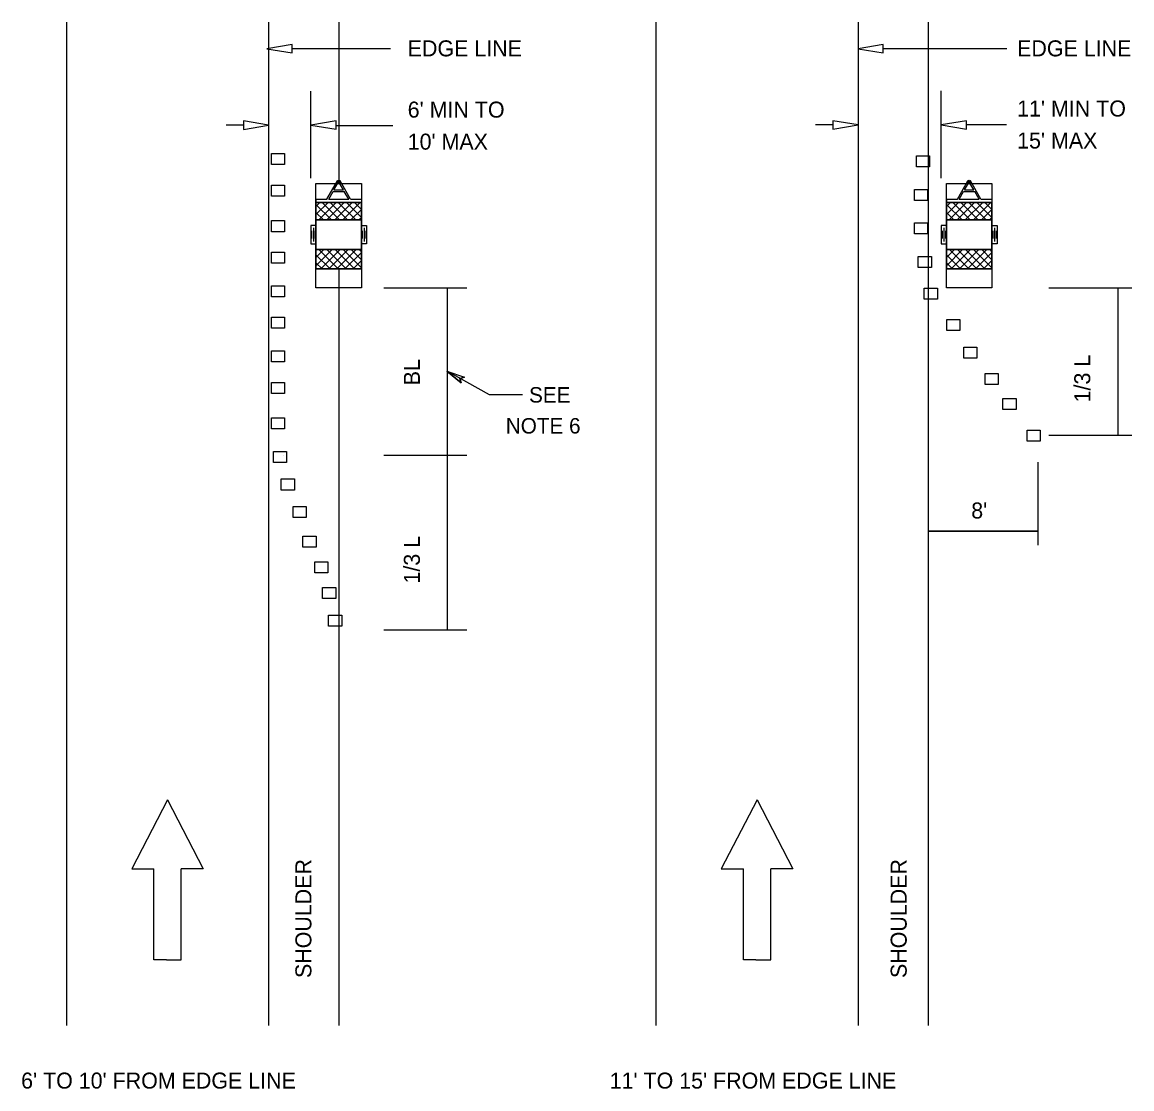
# Model space of a CAD drawing. Extents: x 9 to 25.8, y 6 to 22.7.
# Drawn here: x 21.457 to 25.758, y 11.055 to 15.19 of the extents above; entities that cross this region are included whole.
import ezdxf

# ---------------------------------------------------------------- set-up
doc = ezdxf.new("R2010")
doc.units = 0
for name, color, linetype in [('C-SIGN-FACE_N', 7, 'Continuous'), ('DETL-DIMS', 7, 'Continuous'), ('DETL-LINE', 7, 'Continuous'), ('DETL-NOTE', 7, 'Continuous'), ('SIGN-FACE_P', 7, 'Continuous'), ('SIGN-POST_VSL', 7, 'Continuous'), ('TRAF-MISC', 7, 'Continuous'), ('USER-BORD', 7, 'Continuous')]:
    doc.layers.add(name, color=color, linetype=linetype)

# ---------------------------------------------------------------- blocks, each defined once
blk = doc.blocks.new('DIR2')
at = {"layer": 'USER-BORD'}
for p, q in [((0, 0.0001), (-0.0034, -0.0048)), ((0, 0.0001), (0.0034, -0.0048)), ((-0.0034, -0.0048), (-0.0013, -0.0048)), ((-0.0013, -0.0113), (-0.0013, -0.0048)), ((0.0034, -0.0048), (0.0013, -0.0048)), ((0.0013, -0.0113), (0.0013, -0.0048)), ((-0.0001, -0.0113), (-0.0013, -0.0113)), ((-0.0001, -0.0113), (0.0001, -0.0113)), ((0.0001, -0.0113), (0.0013, -0.0113))]:
    blk.add_line(p, q, dxfattribs=at)

msp = doc.modelspace()

# ---------------------------------------------------------------- linework, layer by layer
at = {"layer": 'C-SIGN-FACE_N'}
for points in [[(22.5956, 14.4912), (22.7718, 14.4912), (22.7718, 14.2335), (22.5956, 14.2335)], [(25.0393, 14.4912), (25.2154, 14.4912), (25.2154, 14.2335), (25.0393, 14.2335)]]:
    msp.add_lwpolyline(points, close=True, dxfattribs=at)
at = {"layer": 'DETL-DIMS'}
for p, q in [((22.5025, 15.0887), (22.8844, 15.0887)), ((24.7931, 15.0887), (25.2736, 15.0887)), ((22.5755, 14.5852), (22.5755, 14.9233)), ((25.0192, 14.5859), (25.0192, 14.924)), ((22.3141, 14.7909), (22.2472, 14.7909)), ((22.6733, 14.789), (22.893, 14.789)), ((24.599, 14.7918), (24.5321, 14.7918)), ((25.116, 14.7934), (25.2724, 14.7934)), ((22.8587, 14.1603), (23.1805, 14.1603)), ((23.1047, 14.1603), (23.1047, 12.8339)), ((23.1047, 14.1603), (23.1047, 13.511)), ((25.4358, 14.1603), (25.7576, 14.1603)), ((25.7029, 14.1603), (25.7029, 13.5895)), ((25.7029, 14.1603), (25.7029, 13.5895)), ((23.1026, 13.8373), (23.1587, 13.7913)), ((23.1026, 13.8373), (23.1711, 13.8132)), ((23.2678, 13.7452), (23.104, 13.837)), ((23.1532, 13.8089), (23.1711, 13.8132)), ((23.1587, 13.7913), (23.1532, 13.8089)), ((23.396, 13.7452), (23.2678, 13.7452)), ((25.4358, 13.5895), (25.7576, 13.5895)), ((22.8587, 13.511), (23.1805, 13.511)), ((23.1047, 13.511), (23.1047, 12.8339)), ((25.3931, 13.4841), (25.3931, 13.1623)), ((24.9685, 13.217), (25.3931, 13.217)), ((25.3931, 13.217), (24.9685, 13.217)), ((22.8587, 12.8339), (23.1805, 12.8339))]:
    msp.add_line(p, q, dxfattribs=at)
for points in [[(22.5038, 15.0707), (22.5038, 15.1034), (22.4058, 15.087)], [(24.7944, 15.0707), (24.7944, 15.1034), (24.6964, 15.087)], [(22.3141, 14.8073), (22.3141, 14.7746), (22.4121, 14.7909)], [(22.6736, 14.7747), (22.6736, 14.8074), (22.5755, 14.791)], [(24.599, 14.8081), (24.599, 14.7754), (24.697, 14.7918)], [(25.1172, 14.7754), (25.1172, 14.8081), (25.0192, 14.7918)], [(23.1587, 13.7913), (23.1026, 13.8373), (23.1711, 13.8132), (23.1532, 13.8089)]]:
    msp.add_lwpolyline(points, close=True, dxfattribs=at)
at = {"layer": 'DETL-LINE'}
for p, q in [((21.6284, 15.1901), (21.6284, 11.3001)), ((22.4121, 15.1901), (22.4121, 11.3001)), ((22.6837, 15.1901), (22.6837, 14.5775)), ((23.9133, 15.1901), (23.9133, 11.3001)), ((24.697, 15.1901), (24.697, 11.3001)), ((24.9685, 15.1901), (24.9685, 11.3001)), ((22.6837, 14.2335), (22.6837, 11.3001)), ((22.4685, 13.511), (22.4685, 13.511))]:
    msp.add_line(p, q, dxfattribs=at)
for points in [[(22.4228, 14.6379), (22.4228, 14.6807), (22.4738, 14.6807), (22.4738, 14.6379)], [(24.9225, 14.629), (24.9225, 14.6718), (24.9735, 14.6718), (24.9735, 14.629)], [(22.4228, 14.5156), (22.4228, 14.5583), (22.4738, 14.5583), (22.4738, 14.5156)], [(24.9148, 14.499), (24.9148, 14.5418), (24.9657, 14.5418), (24.9657, 14.499)], [(22.4228, 14.3779), (22.4228, 14.4207), (22.4738, 14.4207), (22.4738, 14.3779)], [(24.9148, 14.369), (24.9148, 14.4118), (24.9657, 14.4118), (24.9657, 14.369)], [(22.4228, 14.2555), (22.4228, 14.2984), (22.4738, 14.2984), (22.4738, 14.2555)], [(24.9302, 14.239), (24.9302, 14.2818), (24.9811, 14.2818), (24.9811, 14.239)], [(22.4228, 14.1256), (22.4228, 14.1684), (22.4738, 14.1684), (22.4738, 14.1256)], [(24.953, 14.1167), (24.953, 14.1595), (25.004, 14.1595), (25.004, 14.1167)], [(22.4228, 14.0032), (22.4228, 14.0461), (22.4738, 14.0461), (22.4738, 14.0032)], [(25.0405, 13.9943), (25.0405, 14.0371), (25.0914, 14.0371), (25.0914, 13.9943)], [(22.4228, 13.8731), (22.4228, 13.916), (22.4738, 13.916), (22.4738, 13.8731)], [(25.1063, 13.8872), (25.1063, 13.9301), (25.1573, 13.9301), (25.1573, 13.8872)], [(25.1889, 13.7853), (25.1889, 13.8281), (25.2399, 13.8281), (25.2399, 13.7853)], [(22.4228, 13.7508), (22.4228, 13.7937), (22.4738, 13.7937), (22.4738, 13.7508)], [(25.2581, 13.6885), (25.2581, 13.7312), (25.309, 13.7312), (25.309, 13.6885)], [(22.4228, 13.6132), (22.4228, 13.6561), (22.4738, 13.6561), (22.4738, 13.6132)], [(25.3516, 13.566), (25.3516, 13.6089), (25.4025, 13.6089), (25.4025, 13.566)], [(22.4306, 13.4832), (22.4306, 13.526), (22.4815, 13.526), (22.4815, 13.4832)], [(22.4611, 13.3761), (22.4611, 13.419), (22.512, 13.419), (22.512, 13.3761)], [(22.5069, 13.2691), (22.5069, 13.3119), (22.5578, 13.3119), (22.5578, 13.2691)], [(22.5451, 13.1544), (22.5451, 13.1973), (22.596, 13.1973), (22.596, 13.1544)], [(22.5911, 13.0549), (22.5911, 13.0978), (22.6419, 13.0978), (22.6419, 13.0549)], [(22.6215, 12.9556), (22.6215, 12.9984), (22.6724, 12.9984), (22.6724, 12.9556)], [(22.6445, 12.8485), (22.6445, 12.8914), (22.6954, 12.8914), (22.6954, 12.8485)]]:
    msp.add_lwpolyline(points, close=True, dxfattribs=at)
at = {"layer": 'SIGN-FACE_P'}
for p, q in [((22.5956, 14.5044), (22.5956, 14.4912)), ((22.7718, 14.5044), (22.7718, 14.4912)), ((25.0393, 14.5044), (25.0393, 14.4912)), ((25.2154, 14.5044), (25.2154, 14.4912))]:
    msp.add_line(p, q, dxfattribs=at)
at = {"layer": 'SIGN-POST_VSL'}
for points in [[(22.5956, 14.5643), (22.7718, 14.5643), (22.7718, 14.1603), (22.5956, 14.1603)], [(25.0393, 14.5643), (25.2154, 14.5643), (25.2154, 14.1603), (25.0393, 14.1603)]]:
    msp.add_lwpolyline(points, close=True, dxfattribs=at)
at = {"layer": 'TRAF-MISC'}
for p, q in [((22.6381, 14.5044), (22.6786, 14.5746)), ((22.6653, 14.5397), (22.6808, 14.5665)), ((22.6653, 14.5397), (22.7021, 14.5397)), ((22.7021, 14.5397), (22.6867, 14.5665)), ((22.7294, 14.5044), (22.6888, 14.5746)), ((25.0817, 14.5044), (25.1222, 14.5746)), ((25.1089, 14.5397), (25.1244, 14.5665)), ((25.1089, 14.5397), (25.1458, 14.5397)), ((25.1458, 14.5397), (25.1303, 14.5665)), ((25.173, 14.5044), (25.1324, 14.5746)), ((22.5956, 14.5044), (22.6381, 14.5044)), ((22.6449, 14.5044), (22.6619, 14.5338)), ((22.6449, 14.5044), (22.7225, 14.5044)), ((22.6619, 14.5338), (22.7055, 14.5338)), ((22.7225, 14.5044), (22.7055, 14.5338)), ((22.7294, 14.5044), (22.7718, 14.5044)), ((25.0393, 14.5044), (25.0817, 14.5044)), ((25.0885, 14.5044), (25.1055, 14.5338)), ((25.0885, 14.5044), (25.1662, 14.5044)), ((25.1055, 14.5338), (25.1492, 14.5338)), ((25.1662, 14.5044), (25.1492, 14.5338)), ((25.173, 14.5044), (25.2154, 14.5044)), ((22.5956, 14.4912), (22.5956, 14.4236)), ((22.5956, 14.4444), (22.6424, 14.4912)), ((22.5956, 14.4757), (22.6111, 14.4912)), ((22.5956, 14.4839), (22.6559, 14.4236)), ((22.5956, 14.4526), (22.6247, 14.4236)), ((22.6061, 14.4236), (22.6736, 14.4912)), ((22.6196, 14.4912), (22.6872, 14.4236)), ((22.6373, 14.4236), (22.7049, 14.4912)), ((22.6509, 14.4912), (22.7184, 14.4236)), ((22.6686, 14.4236), (22.7361, 14.4912)), ((22.6821, 14.4912), (22.7497, 14.4236)), ((22.6998, 14.4236), (22.7674, 14.4912)), ((22.7134, 14.4912), (22.7718, 14.4328)), ((22.7311, 14.4236), (22.7718, 14.4643)), ((22.7446, 14.4912), (22.7718, 14.4641)), ((25.0393, 14.4912), (25.0393, 14.4236)), ((25.0393, 14.4444), (25.086, 14.4912)), ((25.0393, 14.4757), (25.0547, 14.4912)), ((25.0393, 14.4839), (25.0996, 14.4236)), ((25.0393, 14.4526), (25.0683, 14.4236)), ((25.0497, 14.4236), (25.1173, 14.4912)), ((25.0633, 14.4912), (25.1308, 14.4236)), ((25.081, 14.4236), (25.1485, 14.4912)), ((25.0945, 14.4912), (25.1621, 14.4236)), ((25.1122, 14.4236), (25.1798, 14.4912)), ((25.1258, 14.4912), (25.1933, 14.4236)), ((25.1435, 14.4236), (25.211, 14.4912)), ((25.157, 14.4912), (25.2154, 14.4328)), ((25.1747, 14.4236), (25.2154, 14.4643)), ((25.1883, 14.4912), (25.2154, 14.4641)), ((22.5956, 14.4236), (22.7718, 14.4236)), ((22.7623, 14.4236), (22.7718, 14.433)), ((25.0393, 14.4236), (25.2154, 14.4236)), ((25.206, 14.4236), (25.2154, 14.433)), ((22.5787, 14.381), (22.5787, 14.351)), ((22.5856, 14.3926), (22.5856, 14.3393)), ((22.5925, 14.381), (22.5925, 14.351)), ((22.7749, 14.381), (22.7749, 14.351)), ((22.7818, 14.3926), (22.7818, 14.3393)), ((22.7887, 14.381), (22.7887, 14.351)), ((25.0223, 14.381), (25.0223, 14.351)), ((25.0292, 14.3926), (25.0292, 14.3393)), ((25.0361, 14.381), (25.0361, 14.351)), ((25.2185, 14.381), (25.2185, 14.351)), ((25.2254, 14.3926), (25.2254, 14.3393)), ((25.2324, 14.381), (25.2324, 14.351)), ((22.7718, 14.3083), (22.5956, 14.3083)), ((22.5956, 14.246), (22.6579, 14.3083)), ((22.5956, 14.2773), (22.6267, 14.3083)), ((22.5956, 14.2884), (22.6506, 14.2335)), ((22.607, 14.3083), (22.6819, 14.2335)), ((22.6143, 14.2335), (22.6892, 14.3083)), ((22.6383, 14.3083), (22.7131, 14.2335)), ((22.6456, 14.2335), (22.7204, 14.3083)), ((22.6695, 14.3083), (22.7444, 14.2335)), ((22.6768, 14.2335), (22.7517, 14.3083)), ((22.7008, 14.3083), (22.7718, 14.2373)), ((22.7081, 14.2335), (22.7718, 14.2971)), ((22.732, 14.3083), (22.7718, 14.2686)), ((22.7633, 14.3083), (22.7718, 14.2999)), ((22.7718, 14.2335), (22.7718, 14.3083)), ((25.2154, 14.3083), (25.0393, 14.3083)), ((25.0393, 14.246), (25.1016, 14.3083)), ((25.0393, 14.2773), (25.0703, 14.3083)), ((25.0393, 14.2884), (25.0942, 14.2335)), ((25.0506, 14.3083), (25.1255, 14.2335)), ((25.058, 14.2335), (25.1328, 14.3083)), ((25.0819, 14.3083), (25.1567, 14.2335)), ((25.0892, 14.2335), (25.1641, 14.3083)), ((25.1132, 14.3083), (25.188, 14.2335)), ((25.1205, 14.2335), (25.1953, 14.3083)), ((25.1444, 14.3083), (25.2154, 14.2373)), ((25.1517, 14.2335), (25.2154, 14.2971)), ((25.1757, 14.3083), (25.2154, 14.2686)), ((25.2069, 14.3083), (25.2154, 14.2999)), ((25.2154, 14.2335), (25.2154, 14.3083)), ((22.5956, 14.2572), (22.6193, 14.2335)), ((22.7394, 14.2335), (22.7718, 14.2659)), ((25.0393, 14.2572), (25.063, 14.2335)), ((25.183, 14.2335), (25.2154, 14.2659)), ((22.7706, 14.2335), (22.7718, 14.2346)), ((25.2142, 14.2335), (25.2154, 14.2346))]:
    msp.add_line(p, q, dxfattribs=at)
for points in [[(22.5956, 14.4912), (22.5956, 14.2335), (22.7718, 14.2335), (22.7718, 14.4912)], [(22.5956, 14.4912), (22.7718, 14.4912), (22.7718, 14.4236), (22.5956, 14.4236)], [(25.0393, 14.4912), (25.0393, 14.2335), (25.2154, 14.2335), (25.2154, 14.4912)], [(25.0393, 14.4912), (25.2154, 14.4912), (25.2154, 14.4236), (25.0393, 14.4236)], [(22.5956, 14.4015), (22.5755, 14.4015), (22.5755, 14.3304), (22.5956, 14.3304)], [(22.7718, 14.4015), (22.7919, 14.4015), (22.7919, 14.3304), (22.7718, 14.3304)], [(25.0393, 14.4015), (25.0192, 14.4015), (25.0192, 14.3304), (25.0393, 14.3304)], [(25.2154, 14.4015), (25.2355, 14.4015), (25.2355, 14.3304), (25.2154, 14.3304)], [(22.5956, 14.3083), (22.7718, 14.3083), (22.7718, 14.2335), (22.5956, 14.2335)], [(25.0393, 14.3083), (25.2154, 14.3083), (25.2154, 14.2335), (25.0393, 14.2335)]]:
    msp.add_lwpolyline(points, close=True, dxfattribs=at)
for points in [[(22.7718, 14.4236), (22.7718, 14.4912), (22.5956, 14.4912)], [(25.2154, 14.4236), (25.2154, 14.4912), (25.0393, 14.4912)], [(22.5956, 14.3083), (22.5956, 14.2335), (22.7718, 14.2335)], [(25.0393, 14.3083), (25.0393, 14.2335), (25.2154, 14.2335)]]:
    msp.add_lwpolyline(points, dxfattribs=at)
for centre, radius in [((22.6837, 14.5716), 0.00589), ((22.6837, 14.5716), 0.00295), ((22.6837, 14.5716), 0.00177), ((25.1273, 14.5716), 0.00589), ((25.1273, 14.5716), 0.00295), ((25.1273, 14.5716), 0.00177)]:
    msp.add_circle(centre, radius, dxfattribs=at)

# ---------------------------------------------------------------- block references
at = {"layer": 'DETL-LINE', "xscale": 40.80078878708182, "yscale": 54.4010517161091, "rotation": 1.0739341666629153e-12}
for p in [(22.0203, 12.1691), (24.3051, 12.1691)]:
    msp.add_blockref('DIR2', p, dxfattribs=at)

# ---------------------------------------------------------------- texts
at = {"layer": 'DETL-NOTE'}
for s, height, p in [('EDGE LINE', 0.06207, (22.9511, 15.0576)), ('EDGE LINE', 0.06207, (25.3131, 15.0576)), ("6' MIN TO", 0.06207, (22.9511, 14.8201)), ("11' MIN TO", 0.06207, (25.3131, 14.8244)), ("10' MAX", 0.06207, (22.9511, 14.6959)), ("15' MAX", 0.06207, (25.3131, 14.7003)), ("8'", 0.06207, (25.1353, 13.2658)), ("6' TO 10' FROM EDGE LINE", 0.062069, (21.4528, 11.0555)), ("11' TO 15' FROM EDGE LINE", 0.062069, (23.7339, 11.0555))]:
    msp.add_text(s, height=height, dxfattribs=at).set_placement(p)
for s, height, rotation, p in [('1/3 L', 0.06207, 90, (25.5966, 13.7161)), ('BL', 0.06207, 90, (22.9984, 13.7824)), ('SEE ', 0.06, 359.9944, (23.4214, 13.7152)), ('NOTE 6', 0.06, 359.9944, (23.3313, 13.5952)), ('1/3 L', 0.06207, 90, (22.9984, 13.0137)), ('SHOULDER', 0.06207, 90, (22.5779, 11.4841)), ('SHOULDER', 0.06207, 90, (24.8851, 11.4841))]:
    msp.add_text(s, height=height, rotation=rotation, dxfattribs=at).set_placement(p)

doc.saveas('drawing.dxf')
